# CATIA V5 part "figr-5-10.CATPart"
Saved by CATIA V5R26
Part number: Part1
Bounding box of the stored display mesh (mm): x 0 to 150, y -70 to 70, z -150 to 69.804
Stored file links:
  D:\_Deepak\CATIA\CATIA V5-6R2016_Deepak\Resources\Part files\Partfiles\c05_catia_v5_6r2016_prt\figr-5-10.CATPart
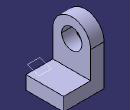
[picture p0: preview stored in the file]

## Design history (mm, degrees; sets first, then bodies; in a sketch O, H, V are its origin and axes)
Set1
  Plane1: type 2Lines, Element1 edge of Pad2, Element2 edge of Pad2
Body1 (main body)
  Sketch1 on yz-plane, origin (0, 0, 0), H (0, 1, 0), V (0, 0, 1)
    arc A1 centre (0, 0) radius 70 from (70, 0) to (-70, 0) ccw
    point P1 (70, 0)
    point P2 (-70, 0)
    line L1 (-70, 0) -> (-70, -150)
    line L2 (-70, -150) -> (70, -150)
    line L3 (70, -150) -> (70, 0)
    circle A2 centre (0, 0) radius 37.5
    radius A1 = 70
    radius A2 = 37.5
    distance O L2 = 150
    coincidence: P1 H, P2 H
    tangency: L1 A1, L3 A1
    horizontal: L2 H
  Pad1: profile Sketch1, direction (1, 0, 0), length 50
  Sketch2 on face of Pad1, origin (50, 0, 0), H (0, 1, 0), V (0, 0, 1)
    line L1 (-70, -150) -> (70, -150)
    line L2 (70, -150) -> (70, -100)
    line L3 (70, -100) -> (-70, -100)
    line L4 (-70, -100) -> (-70, -150)
    reference projected line E1 (-70, -150) -> (70, -150) from edge [face of Pad1 | face of Pad1]
    reference projected line E2 (-70, 0) -> (-70, -150) from edge [face of Pad1 | face of Pad1]
    reference projected line E3 (70, -150) -> (70, 0) from edge [face of Pad1 | face of Pad1]
    length L2 = 50
    horizontal: L1 H, L3 H
    vertical: L2 V, L4 V
    coincidence: L1 E1, E2 L4, L2 E3
  Pad2: profile Sketch2, direction (1, 0, 0), length 100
